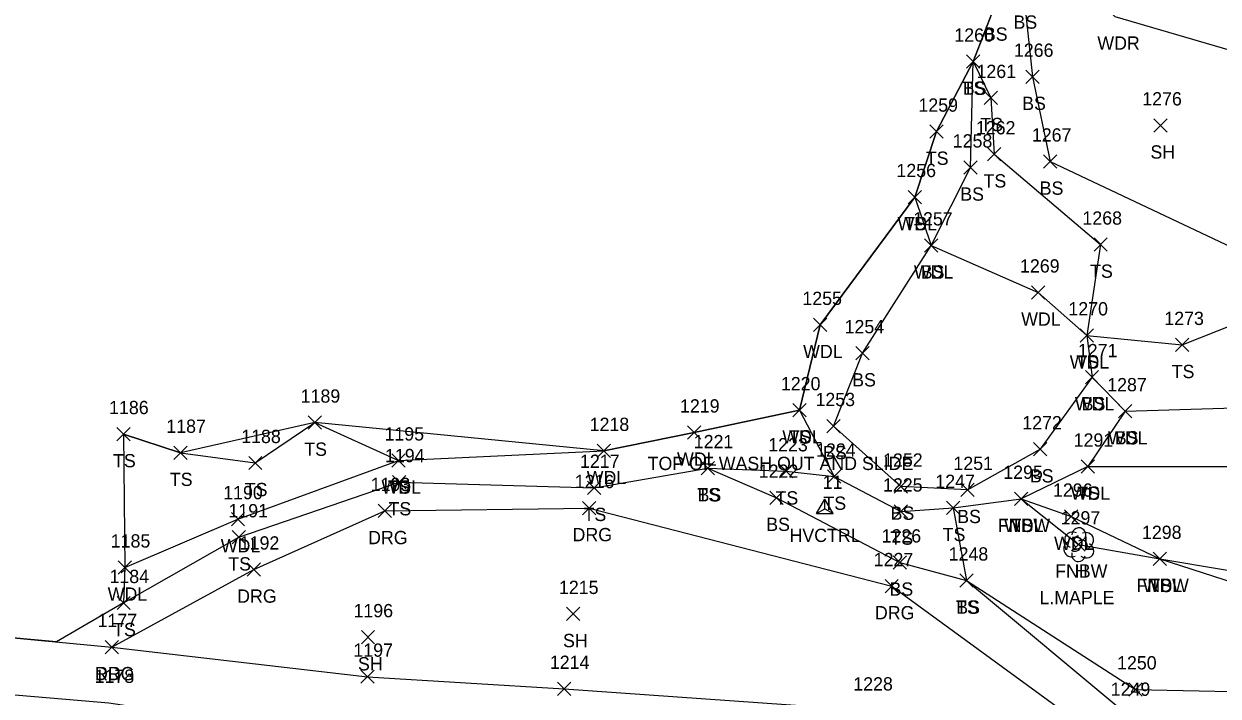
# Model space of a CAD drawing. Extents: x 1600281 to 1602254, y 862855 to 863227.
# Drawn here: x 1601747.6 to 1601927.2, y 862948.7 to 863049.8 of the extents above; entities that cross this region are included whole.
import ezdxf

# ---------------------------------------------------------------- set-up
doc = ezdxf.new("R2010")
doc.units = 0
for name, color, linetype in [('C_A', 7, 'Continuous'), ('C_I', 7, 'Continuous'), ('CPSM', 7, 'Continuous'), ('L_A', 7, 'Continuous'), ('L_C', 7, 'Continuous'), ('L_I', 7, 'Continuous'), ('L_TIC', 7, 'Continuous'), ('LAWA', 7, 'Continuous'), ('LELB', 7, 'Continuous'), ('LFNC', 7, 'Continuous'), ('LSOGP', 7, 'Continuous'), ('LTD', 7, 'Continuous'), ('P_A', 7, 'Continuous'), ('P_I', 7, 'Continuous'), ('P_TIC', 7, 'Continuous'), ('PEU', 7, 'Continuous'), ('PRC', 7, 'Continuous'), ('R_A', 7, 'Continuous'), ('R_I', 7, 'Continuous'), ('R_TIC', 7, 'Continuous'), ('RDG', 7, 'Continuous')]:
    doc.layers.add(name, color=color, linetype=linetype)

msp = doc.modelspace()

# ---------------------------------------------------------------- linework, layer by layer
at = {"layer": 'CPSM'}
for p, q in [((1601866.82, 862976.14), (1601868.07, 862978.31)), ((1601869.32, 862976.14), (1601868.07, 862978.31)), ((1601868.07, 862976.86), (1601868.07, 862978.31)), ((1601866.82, 862976.14), (1601868.07, 862976.86)), ((1601866.82, 862976.14), (1601869.32, 862976.14)), ((1601868.07, 862976.86), (1601868.07, 862976.86)), ((1601868.07, 862976.86), (1601869.32, 862976.14))]:
    msp.add_line(p, q, dxfattribs=at)
at = {"layer": 'L_TIC'}
for points in [[(1601889.39, 863043.16), (1601891.39, 863045.16)], [(1601891.39, 863043.16), (1601889.39, 863045.16)], [(1601889.39, 863043.16), (1601891.39, 863045.16)], [(1601891.39, 863043.16), (1601889.39, 863045.16)], [(1601898.32, 863040.88), (1601900.32, 863042.88)], [(1601900.32, 863040.88), (1601898.32, 863042.88)], [(1601892.06, 863037.69), (1601894.06, 863039.69)], [(1601894.06, 863037.69), (1601892.06, 863039.69)], [(1601917.58, 863033.56), (1601919.58, 863035.56)], [(1601919.58, 863033.56), (1601917.58, 863035.56)], [(1601883.86, 863032.62), (1601885.86, 863034.62)], [(1601885.86, 863032.62), (1601883.86, 863034.62)], [(1601892.54, 863029.21), (1601894.54, 863031.21)], [(1601894.54, 863029.21), (1601892.54, 863031.21)], [(1601900.96, 863028.12), (1601902.96, 863030.12)], [(1601902.96, 863028.12), (1601900.96, 863030.12)], [(1601889.01, 863027.23), (1601891.01, 863029.23)], [(1601891.01, 863027.23), (1601889.01, 863029.23)], [(1601880.6, 863022.77), (1601882.6, 863024.77)], [(1601882.6, 863022.77), (1601880.6, 863024.77)], [(1601880.6, 863022.77), (1601882.6, 863024.77)], [(1601882.6, 863022.77), (1601880.6, 863024.77)], [(1601883.06, 863015.5), (1601885.06, 863017.5)], [(1601885.06, 863015.5), (1601883.06, 863017.5)], [(1601883.06, 863015.5), (1601885.06, 863017.5)], [(1601885.06, 863015.5), (1601883.06, 863017.5)], [(1601908.57, 863015.62), (1601910.57, 863017.62)], [(1601910.57, 863015.62), (1601908.57, 863017.62)], [(1601899.19, 863008.41), (1601901.19, 863010.41)], [(1601901.19, 863008.41), (1601899.19, 863010.41)], [(1601866.39, 863003.53), (1601868.39, 863005.53)], [(1601868.39, 863003.53), (1601866.39, 863005.53)], [(1601906.5, 863001.96), (1601908.5, 863003.96)], [(1601908.5, 863001.96), (1601906.5, 863003.96)], [(1601906.5, 863001.96), (1601908.5, 863003.96)], [(1601908.5, 863001.96), (1601906.5, 863003.96)], [(1601920.85, 863000.52), (1601922.85, 863002.52)], [(1601922.85, 863000.52), (1601920.85, 863002.52)], [(1601872.74, 862999.27), (1601874.74, 863001.27)], [(1601874.74, 862999.27), (1601872.74, 863001.27)], [(1601907.27, 862995.67), (1601909.27, 862997.67)], [(1601909.27, 862995.67), (1601907.27, 862997.67)], [(1601907.27, 862995.67), (1601909.27, 862997.67)], [(1601909.27, 862995.67), (1601907.27, 862997.67)], [(1601863.25, 862990.69), (1601865.25, 862992.69)], [(1601865.25, 862990.69), (1601863.25, 862992.69)], [(1601863.25, 862990.69), (1601865.25, 862992.69)], [(1601865.25, 862990.69), (1601863.25, 862992.69)], [(1601912.25, 862990.54), (1601914.25, 862992.54)], [(1601914.25, 862990.54), (1601912.25, 862992.54)], [(1601912.25, 862990.54), (1601914.25, 862992.54)], [(1601914.25, 862990.54), (1601912.25, 862992.54)], [(1601790.35, 862988.83), (1601792.35, 862990.83)], [(1601792.35, 862988.83), (1601790.35, 862990.83)], [(1601868.36, 862988.31), (1601870.36, 862990.31)], [(1601870.36, 862988.31), (1601868.36, 862990.31)], [(1601761.58, 862987.1), (1601763.58, 862989.1)], [(1601763.58, 862987.1), (1601761.58, 862989.1)], [(1601847.43, 862987.34), (1601849.43, 862989.34)], [(1601849.43, 862987.34), (1601847.43, 862989.34)], [(1601833.83, 862984.57), (1601835.83, 862986.57)], [(1601835.83, 862984.57), (1601833.83, 862986.57)], [(1601899.47, 862984.82), (1601901.47, 862986.82)], [(1601901.47, 862984.82), (1601899.47, 862986.82)], [(1601899.47, 862984.82), (1601901.47, 862986.82)], [(1601901.47, 862984.82), (1601899.47, 862986.82)], [(1601770.13, 862984.29), (1601772.13, 862986.29)], [(1601772.13, 862984.29), (1601770.13, 862986.29)], [(1601781.4, 862982.75), (1601783.4, 862984.75)], [(1601783.4, 862982.75), (1601781.4, 862984.75)], [(1601802.96, 862983.13), (1601804.96, 862985.13)], [(1601804.96, 862983.13), (1601802.96, 862985.13)], [(1601802.96, 862983.13), (1601804.96, 862985.13)], [(1601804.96, 862983.13), (1601802.96, 862985.13)], [(1601849.49, 862981.97), (1601851.49, 862983.97)], [(1601851.49, 862981.97), (1601849.49, 862983.97)], [(1601849.49, 862981.97), (1601851.49, 862983.97)], [(1601851.49, 862981.97), (1601849.49, 862983.97)], [(1601861.25, 862981.5), (1601863.25, 862983.5)], [(1601863.25, 862981.5), (1601861.25, 862983.5)], [(1601906.64, 862982.21), (1601908.64, 862984.21)], [(1601908.64, 862982.21), (1601906.64, 862984.21)], [(1601906.64, 862982.21), (1601908.64, 862984.21)], [(1601908.64, 862982.21), (1601906.64, 862984.21)], [(1601803.03, 862979.87), (1601805.03, 862981.87)], [(1601805.03, 862979.87), (1601803.03, 862981.87)], [(1601832.37, 862979.01), (1601834.37, 862981.01)], [(1601834.37, 862979.01), (1601832.37, 862981.01)], [(1601868.46, 862980.7), (1601870.46, 862982.7)], [(1601870.46, 862980.7), (1601868.46, 862982.7)], [(1601868.46, 862980.7), (1601870.46, 862982.7)], [(1601870.46, 862980.7), (1601868.46, 862982.7)], [(1601878.53, 862979.2), (1601880.53, 862981.2)], [(1601880.53, 862979.2), (1601878.53, 862981.2)], [(1601859.82, 862977.52), (1601861.82, 862979.52)], [(1601861.82, 862977.52), (1601859.82, 862979.52)], [(1601888.55, 862978.7), (1601890.55, 862980.7)], [(1601890.55, 862978.7), (1601888.55, 862980.7)], [(1601888.55, 862978.7), (1601890.55, 862980.7)], [(1601890.55, 862978.7), (1601888.55, 862980.7)], [(1601896.61, 862977.36), (1601898.61, 862979.36)], [(1601898.61, 862977.36), (1601896.61, 862979.36)], [(1601896.61, 862977.36), (1601898.61, 862979.36)], [(1601898.61, 862977.36), (1601896.61, 862979.36)], [(1601896.61, 862977.36), (1601898.61, 862979.36)], [(1601898.61, 862977.36), (1601896.61, 862979.36)], [(1601878.53, 862975.45), (1601880.53, 862977.45)], [(1601880.53, 862975.45), (1601878.53, 862977.45)], [(1601886.39, 862975.99), (1601888.39, 862977.99)], [(1601888.39, 862975.99), (1601886.39, 862977.99)], [(1601886.39, 862975.99), (1601888.39, 862977.99)], [(1601888.39, 862975.99), (1601886.39, 862977.99)], [(1601778.79, 862974.29), (1601780.79, 862976.29)], [(1601780.79, 862974.29), (1601778.79, 862976.29)], [(1601904.15, 862974.68), (1601906.15, 862976.68)], [(1601906.15, 862974.68), (1601904.15, 862976.68)], [(1601778.92, 862971.57), (1601780.92, 862973.57)], [(1601780.92, 862971.57), (1601778.92, 862973.57)], [(1601905.25, 862970.5), (1601907.25, 862972.5)], [(1601907.25, 862970.5), (1601905.25, 862972.5)], [(1601917.48, 862968.32), (1601919.48, 862970.32)], [(1601919.48, 862968.32), (1601917.48, 862970.32)], [(1601917.48, 862968.32), (1601919.48, 862970.32)], [(1601919.48, 862968.32), (1601917.48, 862970.32)], [(1601917.48, 862968.32), (1601919.48, 862970.32)], [(1601919.48, 862968.32), (1601917.48, 862970.32)], [(1601761.77, 862967.02), (1601763.77, 862969.02)], [(1601763.77, 862967.02), (1601761.77, 862969.02)], [(1601878.36, 862967.78), (1601880.36, 862969.78)], [(1601880.36, 862967.78), (1601878.36, 862969.78)], [(1601888.4, 862965.06), (1601890.4, 862967.06)], [(1601890.4, 862965.06), (1601888.4, 862967.06)], [(1601888.4, 862965.06), (1601890.4, 862967.06)], [(1601890.4, 862965.06), (1601888.4, 862967.06)], [(1601761.59, 862961.68), (1601763.59, 862963.68)], [(1601763.59, 862961.68), (1601761.59, 862963.68)], [(1601829.2, 862960.03), (1601831.2, 862962.03)], [(1601831.2, 862960.03), (1601829.2, 862962.03)], [(1601798.35, 862956.53), (1601800.35, 862958.53)], [(1601800.35, 862956.53), (1601798.35, 862958.53)], [(1601913.82, 862948.68), (1601915.82, 862950.68)], [(1601915.82, 862948.68), (1601913.82, 862950.68)]]:
    msp.add_lwpolyline(points, dxfattribs=at)
at = {"layer": 'LAWA'}
for points in [[(1601898.68, 863064.42), (1601911.71, 863050.95), (1601935.9, 863043.88), (1601947.49, 863033.02), (1601951.4, 863041.53), (1601951.33, 863053.2), (1601949.99, 863060.09), (1601958.57, 863066.85), (1601964.29, 863071.52), (1601970.83, 863066.79), (1601979.18, 863061.54), (1601987.87, 863058.21), (1601991.58, 863057.22), (1602006.6, 863051.13), (1602014.67, 863047.98), (1602025.68, 863046.6), (1602024.95, 863036.82), (1602020.12, 863030.26)], [(1601762.77, 862968.02), (1601779.79, 862975.29), (1601803.96, 862984.13), (1601834.83, 862985.57), (1601848.43, 862988.34), (1601864.25, 862991.69), (1601867.39, 863004.53), (1601881.6, 863023.77), (1601884.06, 863016.5), (1601900.19, 863009.41), (1601907.5, 863002.96), (1601908.27, 862996.67), (1601913.25, 862991.54), (1601907.64, 862983.21), (1601897.61, 862978.36), (1601905.15, 862975.68), (1601918.48, 862969.32), (1601939.42, 862962.53)]]:
    msp.add_lwpolyline(points, dxfattribs=at)
at = {"layer": 'LELB'}
for points in [[(1601889.55, 862979.7), (1601879.53, 862980.2), (1601869.36, 862989.31), (1601873.74, 863000.27), (1601884.06, 863016.5), (1601890.01, 863028.23), (1601890.39, 863044.16), (1601893.55, 863052.3), (1601898.68, 863064.42), (1601898, 863054.11), (1601899.32, 863041.88), (1601901.96, 863029.12), (1601931.06, 863015.37), (1601935.9, 863043.88), (1601936.52, 863051.72)], [(1601850.49, 862982.97), (1601860.82, 862978.52), (1601879.36, 862968.78), (1601889.4, 862966.06), (1601913.79, 862945.71), (1601936.18, 862934.79), (1601959, 862928.54), (1601973.11, 862927.74), (1601983.04, 862929.48), (1601994.91, 862935.46), (1602008.18, 862945.23), (1602016.32, 862961.34), (1602018.76, 862980.32), (1602014.94, 863002.44), (1602007.85, 863017.62), (1602006.36, 863023.32), (1602003.16, 863037.99), (1602002.76, 863044.77), (1602006.6, 863051.13), (1602010.65, 863053.19)], [(1601881.6, 863023.77), (1601884.86, 863033.62), (1601890.39, 863044.16), (1601893.06, 863038.69), (1601893.54, 863030.21), (1601909.57, 863016.62), (1601907.5, 863002.96), (1601921.85, 863001.52), (1601937.52, 863007.75), (1601947.49, 863033.02)], [(1601913.25, 862991.54), (1601936.33, 862992.23), (1601953.07, 863003.06), (1601968.85, 863011.82), (1601988.46, 863008.93)], [(1601908.27, 862996.67), (1601900.47, 862985.82)], [(1601864.25, 862991.69), (1601869.46, 862981.7)], [(1601762.58, 862988.1), (1601771.13, 862985.29), (1601782.4, 862983.75), (1601791.35, 862989.83), (1601803.96, 862984.13)], [(1601907.64, 862983.21), (1601932.18, 862983.24), (1601948.6, 862984.2), (1601979.1, 862987.73), (1601984.53, 862976.52), (1601990.97, 862965.7)], [(1601889.55, 862979.7), (1601900.47, 862985.82)], [(1601762.59, 862962.68), (1601779.92, 862972.57), (1601804.03, 862980.87), (1601833.37, 862980.01), (1601850.49, 862982.97), (1601862.25, 862982.5), (1601869.46, 862981.7), (1601879.53, 862976.45), (1601887.39, 862976.99), (1601889.4, 862966.06), (1601914.82, 862949.68), (1601938.71, 862949.15), (1601955.99, 862947.41), (1601966.62, 862951.39), (1601981.96, 862959.59)], [(1601887.39, 862976.99), (1601897.61, 862978.36)], [(1601918.48, 862969.32), (1601957.37, 862962.83), (1601968.02, 862964.16), (1601976.47, 862966.64), (1601981.96, 862959.59)]]:
    msp.add_lwpolyline(points, dxfattribs=at)
at = {"layer": 'LFNC'}
msp.add_lwpolyline([(1601897.61, 862978.36), (1601906.25, 862971.5), (1601918.48, 862969.32)], dxfattribs=at)
at = {"layer": 'LSOGP'}
msp.add_lwpolyline([(1601893.55, 863052.3), (1601890.39, 863044.16), (1601884.86, 863033.62), (1601881.6, 863023.77), (1601867.39, 863004.53), (1601864.25, 862991.69), (1601848.43, 862988.34), (1601834.83, 862985.57), (1601791.35, 862989.83), (1601771.13, 862985.29), (1601762.58, 862988.1), (1601762.77, 862968.02), (1601762.59, 862962.68), (1601752.51, 862956.82), (1601742.56, 862957.76)], dxfattribs=at)
at = {"layer": 'LTD'}
msp.add_line((1601906.25, 862971.5), (1601906.25, 862971.5), dxfattribs=at)
msp.add_line((1601906.25, 862971.5), (1601906.25, 862971.5), dxfattribs=at)
msp.add_arc((1601906.3, 862972.94), 1.05, 335.5272, 180.9563, dxfattribs=at)
for centre, major_axis, ratio, start_param, end_param in [((1601905.46, 862972.17), (1.21, -0.51), 0.895232, 1.570796, 4.712389), ((1601906.04, 862971.96), (-0.208, -0.792), 0.645439, 3.141593, 6.283185), ((1601906.75, 862971.34), (-0.5, 0.667), 0.989748, 3.141593, 6.283185), ((1601907.29, 862972.09), (-1.14, -0.48), 0.949671, 1.570796, 4.712389), ((1601905.17, 862970.79), (0.58, -1.04), 0.959034, 3.141593, 6.283185), ((1601906.25, 862970), (0.26, 1.06), 0.942809, 1.570796, 4.712389), ((1601905.79, 862970.75), (-0.625, -0.083), 0.423636, 0, 3.141593), ((1601907.25, 862970.67), (-1.09, 0.79), 0.841452, 1.570796, 4.712389)]:
    msp.add_ellipse(centre, major_axis=major_axis, ratio=ratio, start_param=start_param, end_param=end_param, dxfattribs=at)
at = {"layer": 'P_TIC'}
for points in [[(1601759.79, 862955.05), (1601761.79, 862957.05)], [(1601761.79, 862955.05), (1601759.79, 862957.05)], [(1601798.29, 862950.59), (1601800.29, 862952.59)], [(1601800.29, 862950.59), (1601798.29, 862952.59)], [(1601827.84, 862948.76), (1601829.84, 862950.76)], [(1601829.84, 862948.76), (1601827.84, 862950.76)]]:
    msp.add_lwpolyline(points, dxfattribs=at)
at = {"layer": 'PEU'}
msp.add_lwpolyline([(1601722.64, 862959.62), (1601760.79, 862956.05), (1601799.29, 862951.59), (1601828.84, 862949.76), (1601875.05, 862946.51), (1601907.83, 862943.55), (1601935.49, 862931.23), (1601958.79, 862926.46), (1601973.44, 862925.27), (1601984.38, 862925.96), (1601999.67, 862930.14), (1602015.04, 862942.76), (1602018.56, 862960.18), (1602022.83, 862979.22), (1602021.22, 863002.76), (1602025.96, 863016.12), (1602028.23, 863030.49), (1602032.2, 863046.61)], dxfattribs=at)
at = {"layer": 'PRC'}
msp.add_lwpolyline([(1601722.03, 862950.92), (1601760.35, 862947.65), (1601797.64, 862942.06), (1601826.1, 862939.87), (1601874.38, 862936.2), (1601906.56, 862932.66), (1601933.52, 862923.27), (1601957.93, 862920.04), (1601974.08, 862916.23), (1601989.5, 862915.67), (1602005.13, 862920.56), (1602020.05, 862931.21), (1602025.88, 862956.8), (1602029.68, 862975.25), (1602029.18, 863001.63), (1602032.15, 863012.73), (1602036.07, 863028.12), (1602041.55, 863045.82)], dxfattribs=at)
at = {"layer": 'R_TIC'}
for points in [[(1601800.88, 862975.53), (1601802.88, 862977.53)], [(1601802.88, 862975.53), (1601800.88, 862977.53)], [(1601831.63, 862975.97), (1601833.63, 862977.97)], [(1601833.63, 862975.97), (1601831.63, 862977.97)], [(1601781.18, 862966.72), (1601783.18, 862968.72)], [(1601783.18, 862966.72), (1601781.18, 862968.72)], [(1601877.13, 862964.22), (1601879.13, 862966.22)], [(1601879.13, 862964.22), (1601877.13, 862966.22)], [(1601759.79, 862955.05), (1601761.79, 862957.05)], [(1601761.79, 862955.05), (1601759.79, 862957.05)]]:
    msp.add_lwpolyline(points, dxfattribs=at)
at = {"layer": 'RDG'}
msp.add_lwpolyline([(1601760.79, 862956.05), (1601782.18, 862967.72), (1601801.88, 862976.53), (1601832.63, 862976.97), (1601878.13, 862965.22), (1601907.83, 862943.55)], dxfattribs=at)

# ---------------------------------------------------------------- texts
at = {"layer": 'C_A'}
msp.add_text('HVCTRL', height=2, dxfattribs=at).set_placement((1601862.76, 862971.86))
at = {"layer": 'C_I'}
msp.add_text('11', height=2, dxfattribs=at).set_placement((1601867.74, 862979.86))
at = {"layer": 'L_A'}
for s, p in [('BS', (1601896.45, 863049.11)), ('BS', (1601892, 863047.3)), ('WDR', (1601909.07, 863045.95)), ('TS', (1601888.8, 863039.16)), ('BS', (1601888.83, 863039.16)), ('BS', (1601897.76, 863036.88)), ('TS', (1601891.47, 863033.69)), ('SH', (1601917.06, 863029.56)), ('TS', (1601883.27, 863028.62)), ('TS', (1601891.95, 863025.21)), ('BS', (1601900.4, 863024.12)), ('BS', (1601888.45, 863023.23)), ('WDL', (1601879.01, 863018.77)), ('TS', (1601880.01, 863018.77)), ('WDL', (1601881.47, 863011.5)), ('BS', (1601882.5, 863011.5)), ('TS', (1601907.98, 863011.62)), ('WDL', (1601897.61, 863004.41)), ('WDL', (1601864.81, 862999.53)), ('WDL', (1601904.92, 862997.96)), ('TS', (1601905.91, 862997.96)), ('BS', (1601872.19, 862995.27)), ('TS', (1601920.26, 862996.52)), ('WDL', (1601905.69, 862991.67)), ('BS', (1601906.71, 862991.67)), ('WDL', (1601861.67, 862986.69)), ('TS', (1601862.66, 862986.69)), ('WDL', (1601910.67, 862986.54)), ('BS', (1601911.69, 862986.54)), ('TS', (1601789.76, 862984.83)), ('BS', (1601867.8, 862984.31)), ('TS', (1601760.99, 862983.1)), ('WDL', (1601845.84, 862983.34)), ('BS', (1601898.92, 862980.82)), ('BS', (1601898.92, 862980.82)), ('TS', (1601769.54, 862980.29)), ('WDL', (1601801.38, 862979.13)), ('TS', (1601802.37, 862979.13)), ('WDL', (1601832.25, 862980.57)), ('TS', (1601780.81, 862978.75)), ('TS', (1601848.9, 862977.97)), ('BS', (1601848.93, 862977.97)), ('TS', (1601860.66, 862977.5)), ('WDL', (1601905.06, 862978.21)), ('TS', (1601906.05, 862978.21)), ('TS', (1601802.44, 862975.87)), ('TS', (1601867.86, 862976.7)), ('TS', (1601867.86, 862976.7)), ('TS', (1601831.78, 862975.01)), ('BS', (1601859.26, 862973.52)), ('BS', (1601877.97, 862975.2)), ('BS', (1601887.99, 862974.7)), ('BS', (1601887.99, 862974.7)), ('TS', (1601885.8, 862971.99)), ('TS', (1601885.8, 862971.99)), ('FNBW', (1601894.09, 862973.36)), ('WDL', (1601895.03, 862973.36)), ('TS', (1601896.02, 862973.36)), ('WDL', (1601777.2, 862970.29)), ('TS', (1601877.94, 862971.45)), ('WDL', (1601902.56, 862970.68)), ('TS', (1601778.33, 862967.57)), ('FNBW', (1601902.72, 862966.5)), ('H', (1601905.68, 862966.5)), ('WDL', (1601760.19, 862963.02)), ('BS', (1601877.8, 862963.78)), ('FNBW', (1601914.96, 862964.32)), ('WDL', (1601915.9, 862964.32)), ('TS', (1601916.89, 862964.32)), ('TS', (1601887.81, 862961.06)), ('BS', (1601887.84, 862961.06)), ('TS', (1601761, 862957.68)), ('SH', (1601828.69, 862956.03)), ('SH', (1601797.84, 862952.53))]:
    msp.add_text(s, height=2, dxfattribs=at).set_placement(p)
at = {"layer": 'L_C'}
for s, p in [('TOP OF WASH OUT AND SLIDE', (1601841.42, 862982.69)), ('TOP OF WASH OUT AND SLIDE', (1601841.42, 862982.69)), ('L.MAPLE', (1601900.36, 862962.5)), ('L.MAPLE', (1601900.36, 862962.5))]:
    msp.add_text(s, height=2, dxfattribs=at).set_placement(p)
at = {"layer": 'L_I'}
for s, p in [('1260', (1601887.56, 863047.16)), ('1260', (1601887.56, 863047.16)), ('1266', (1601896.52, 863044.88)), ('1261', (1601890.89, 863041.69)), ('1259', (1601882.16, 863036.62)), ('1276', (1601915.83, 863037.56)), ('1262', (1601890.8, 863033.21)), ('1258', (1601887.32, 863031.23)), ('1267', (1601899.22, 863032.12)), ('1256', (1601878.85, 863026.77)), ('1256', (1601878.85, 863026.77)), ('1257', (1601881.36, 863019.5)), ('1257', (1601881.36, 863019.5)), ('1268', (1601906.83, 863019.62)), ('1269', (1601897.44, 863012.41)), ('1255', (1601864.7, 863007.53)), ('1270', (1601904.72, 863005.96)), ('1270', (1601904.72, 863005.96)), ('1273', (1601919.15, 863004.52)), ('1254', (1601871.05, 863003.27)), ('1271', (1601906.14, 862999.67)), ('1271', (1601906.14, 862999.67)), ('1220', (1601861.47, 862994.69)), ('1220', (1601861.47, 862994.69)), ('1287', (1601910.56, 862994.54)), ('1287', (1601910.56, 862994.54)), ('1189', (1601789.22, 862992.83)), ('1253', (1601866.67, 862992.31)), ('1186', (1601760.4, 862991.1)), ('1219', (1601846.29, 862991.34)), ('1187', (1601769.01, 862988.29)), ('1218', (1601832.7, 862988.57)), ('1272', (1601897.78, 862988.82)), ('1272', (1601897.78, 862988.82)), ('1188', (1601780.28, 862986.75)), ('1195', (1601801.83, 862987.13)), ('1195', (1601801.83, 862987.13)), ('1291', (1601905.51, 862986.21)), ('1291', (1601905.51, 862986.21)), ('1221', (1601848.36, 862985.97)), ('1221', (1601848.36, 862985.97)), ('1223', (1601859.56, 862985.5)), ('1224', (1601866.76, 862984.7)), ('1224', (1601866.76, 862984.7)), ('1194', (1601801.91, 862983.87)), ('1217', (1601831.24, 862983.01)), ('1252', (1601876.84, 862983.2)), ('1251', (1601887.42, 862982.7)), ('1251', (1601887.42, 862982.7)), ('1222', (1601858.13, 862981.52)), ('1295', (1601894.92, 862981.36)), ('1295', (1601894.92, 862981.36)), ('1295', (1601894.92, 862981.36)), ('1225', (1601876.83, 862979.45)), ('1247', (1601884.7, 862979.99)), ('1247', (1601884.7, 862979.99)), ('1190', (1601777.57, 862978.29)), ('1296', (1601902.4, 862978.68)), ('1191', (1601778.36, 862975.57)), ('1297', (1601903.56, 862974.5)), ('1297', (1601903.56, 862974.5)), ('1226', (1601876.61, 862971.78)), ('1298', (1601915.79, 862972.32)), ('1298', (1601915.79, 862972.32)), ('1298', (1601915.79, 862972.32)), ('1185', (1601760.65, 862971.02)), ('1248', (1601886.71, 862969.06)), ('1248', (1601886.71, 862969.06)), ('1184', (1601760.46, 862965.68)), ('1215', (1601828.08, 862964.03)), ('1196', (1601797.17, 862960.53)), ('1250', (1601912.04, 862952.68)), ('1249', (1601911.09, 862948.71))]:
    msp.add_text(s, height=2, dxfattribs=at).set_placement(p)
at = {"layer": 'P_A'}
msp.add_text('RDG', height=2, dxfattribs=at).set_placement((1601758.28, 862951.05))
at = {"layer": 'P_I'}
for s, p in [('1177', (1601758.66, 862959.05)), ('1197', (1601797.16, 862954.59)), ('1214', (1601826.71, 862952.76)), ('1178', (1601758.22, 862950.65)), ('1228', (1601872.36, 862949.51))]:
    msp.add_text(s, height=2, dxfattribs=at).set_placement(p)
at = {"layer": 'R_A'}
for p in [(1601830.12, 862971.97), (1601799.37, 862971.53), (1601779.67, 862962.72), (1601875.61, 862960.22), (1601758.28, 862951.05)]:
    msp.add_text('DRG', height=2, dxfattribs=at).set_placement(p)
at = {"layer": 'R_I'}
for s, p in [('1193', (1601799.76, 862979.53)), ('1216', (1601830.45, 862979.97)), ('1192', (1601780.06, 862970.72)), ('1227', (1601875.43, 862968.22)), ('1177', (1601758.66, 862959.05))]:
    msp.add_text(s, height=2, dxfattribs=at).set_placement(p)

doc.saveas('drawing.dxf')
